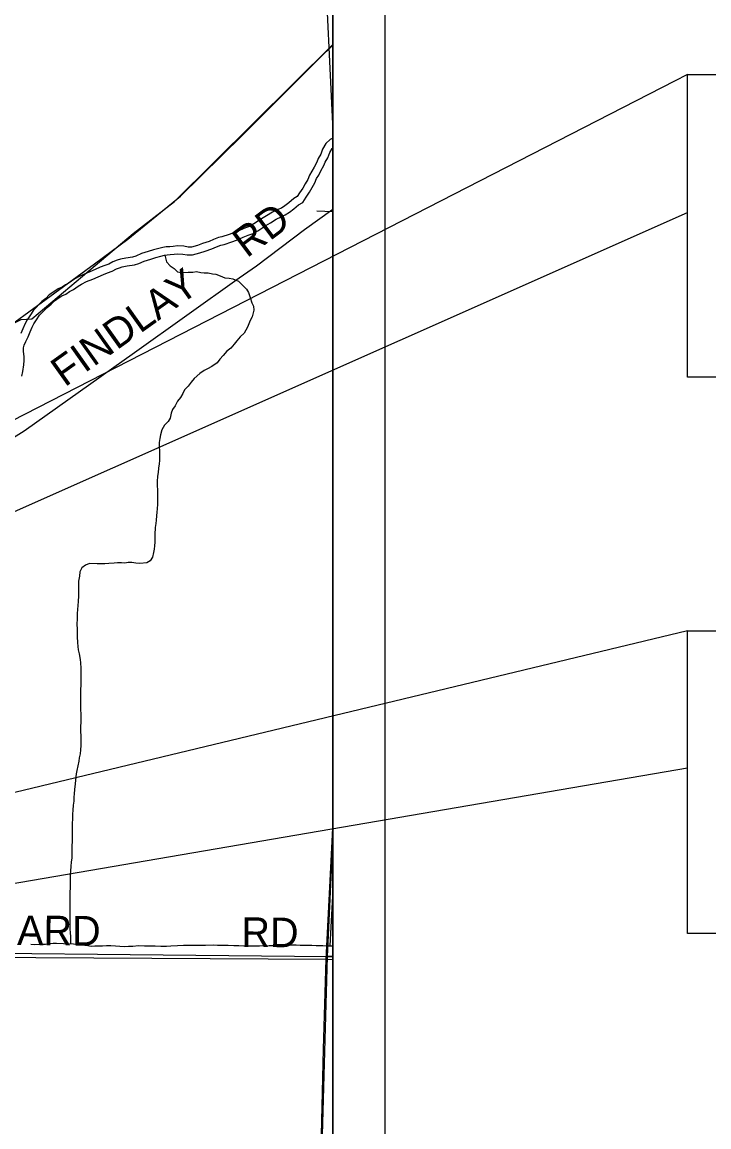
# Model space of a CAD drawing. Extents: x -8.3 to 42.1, y 0 to 22.
# Drawn here: x 8.304 to 9.622, y 16.982 to 19.103 of the extents above; entities that cross this region are included whole.
import ezdxf

# ---------------------------------------------------------------- set-up
doc = ezdxf.new("R2010")
doc.units = 0
for name, color, linetype in [('Default', 7, 'Continuous'), ('GM_X_County_Road', 7, 'Continuous'), ('GM_X_County_Road_Text', 7, 'Continuous'), ('GM_X_Major_River', 7, 'Continuous'), ('GM_X_Minor_River', 7, 'Continuous'), ('GM_X_Rail_Line', 7, 'Continuous'), ('GM_X_Section', 7, 'Continuous'), ('GM_X_State_Route', 7, 'Continuous'), ('GM_X_Township_Road', 7, 'Continuous'), ('SH_Cut_Line', 7, 'Continuous'), ('SH_Data', 7, 'Continuous'), ('SH_Text', 7, 'Continuous')]:
    doc.layers.add(name, color=color, linetype=linetype)

msp = doc.modelspace()

# ---------------------------------------------------------------- linework, layer by layer
at = {"layer": 'Default'}
for points in [[(8.9, 18.8937), (8.9, 19.2548), (8.8831, 19.2542)], [(8.9, 17.309), (8.9, 17.5442), (8.8895, 17.3091)], [(8.9, 16.3044), (8.9, 17.309), (8.8895, 17.3091), (8.8613, 16.3047)]]:
    msp.add_lwpolyline(points, close=True, dxfattribs=at)
at = {"layer": 'GM_X_County_Road'}
for points in [[(7.8987, 17.8473), (7.933, 17.8784), (7.9603, 17.9099), (7.9717, 17.9213), (7.9812, 17.9331), (7.9926, 17.9548), (8.0656, 18.0756), (8.2076, 18.2177), (8.2873, 18.3051), (8.3078, 18.3181), (8.5197, 18.4682), (8.7205, 18.6119), (8.7539, 18.6347), (8.8458, 18.7042), (8.9, 18.7436)], [(7.8831, 17.31), (8.8875, 17.3037), (8.9, 17.3036)]]:
    msp.add_lwpolyline(points, dxfattribs=at)
at = {"layer": 'GM_X_Major_River'}
for points in [[(8.9, 18.8798), (8.8953, 18.8772), (8.8867, 18.8695), (8.8806, 18.8585), (8.8769, 18.849), (8.872, 18.8406), (8.8693, 18.8338), (8.8641, 18.8242), (8.8599, 18.8162), (8.8554, 18.809), (8.852, 18.8006), (8.8471, 18.7923), (8.8426, 18.7839), (8.8362, 18.7747), (8.832, 18.7679), (8.8252, 18.7641), (8.8157, 18.7557), (8.8082, 18.7499)], [(8.8173, 18.7378), (8.8254, 18.7439), (8.8341, 18.7516), (8.8429, 18.7566), (8.8489, 18.7665), (8.8555, 18.7759), (8.8603, 18.7848), (8.8656, 18.7939), (8.8689, 18.8021), (8.8731, 18.8087), (8.8774, 18.8171), (8.8831, 18.8273), (8.8857, 18.834), (8.8905, 18.8423), (8.8944, 18.852), (8.8987, 18.8599), (8.9, 18.8611)], [(8.8082, 18.7499), (8.8017, 18.7457), (8.7945, 18.7426), (8.7843, 18.7376), (8.7726, 18.7304), (8.7635, 18.725), (8.7484, 18.7151), (8.7404, 18.7105), (8.7325, 18.7074), (8.7226, 18.7035), (8.7097, 18.6982), (8.701, 18.6951), (8.6874, 18.6901), (8.6809, 18.6889), (8.6711, 18.685), (8.6627, 18.6816), (8.6502, 18.6773), (8.6404, 18.6739), (8.629, 18.6708), (8.6222, 18.6707), (8.6142, 18.6722), (8.6017, 18.6733), (8.5937, 18.6721), (8.5873, 18.6713), (8.5801, 18.6713), (8.5736, 18.6697), (8.5664, 18.6682), (8.5558, 18.6655), (8.5459, 18.662), (8.5327, 18.6581), (8.5221, 18.6535), (8.5156, 18.6512), (8.5031, 18.6496), (8.4925, 18.6473), (8.486, 18.6457), (8.4781, 18.6427), (8.4701, 18.6381), (8.4622, 18.6354), (8.4538, 18.6319), (8.444, 18.6277), (8.4338, 18.6234), (8.4213, 18.6184), (8.4107, 18.6131), (8.4031, 18.6085), (8.394, 18.6024), (8.3868, 18.5981), (8.3804, 18.5939), (8.3728, 18.5905), (8.3664, 18.5863), (8.3558, 18.579), (8.3493, 18.5721), (8.3418, 18.566), (8.3255, 18.5496), (8.3184, 18.5389), (8.3135, 18.5309), (8.3093, 18.5241), (8.3052, 18.5138), (8.3014, 18.5047)], [(8.3029, 18.423), (8.3052, 18.4321), (8.3072, 18.4449), (8.3077, 18.453), (8.3076, 18.4608), (8.3065, 18.4706), (8.3064, 18.4771), (8.3079, 18.4823), (8.3107, 18.4893), (8.3152, 18.4984), (8.3192, 18.5081), (8.3229, 18.5173), (8.3264, 18.5231), (8.3311, 18.5308), (8.3373, 18.54), (8.352, 18.5548), (8.3597, 18.561), (8.3657, 18.5674), (8.3748, 18.5737), (8.3801, 18.5772), (8.3877, 18.5806), (8.3948, 18.5852), (8.4021, 18.5895), (8.4113, 18.5957), (8.418, 18.5998), (8.4275, 18.6046), (8.4395, 18.6094), (8.4499, 18.6137), (8.4597, 18.6179), (8.4675, 18.6212), (8.4764, 18.6242), (8.4847, 18.6289), (8.4906, 18.6312), (8.4959, 18.6325), (8.5057, 18.6347), (8.5192, 18.6364), (8.5277, 18.6394), (8.5378, 18.6438), (8.5506, 18.6476), (8.5602, 18.6509), (8.5699, 18.6534), (8.577, 18.6549), (8.5819, 18.6561), (8.5882, 18.6562), (8.5957, 18.6571), (8.6021, 18.658), (8.6122, 18.6572), (8.6208, 18.6556), (8.6311, 18.6556), (8.6449, 18.6594), (8.6552, 18.663), (8.6681, 18.6674), (8.6767, 18.671), (8.6851, 18.6742), (8.6914, 18.6754), (8.7061, 18.6808), (8.7152, 18.684), (8.7283, 18.6895), (8.7379, 18.6933), (8.747, 18.6968), (8.7563, 18.7022), (8.7715, 18.7121), (8.7804, 18.7174), (8.7917, 18.7244), (8.8009, 18.7288), (8.8089, 18.7323), (8.8173, 18.7378)]]:
    msp.add_lwpolyline(points, dxfattribs=at)
at = {"layer": 'GM_X_Minor_River'}
for p, q in [((8.8695, 18.74), (8.9, 18.7391)), ((8.9, 17.4372), (8.8945, 17.3293))]:
    msp.add_line(p, q, dxfattribs=at)
for points in [[(8.5778, 18.6551), (8.5809, 18.6421), (8.5882, 18.6349), (8.5954, 18.6296), (8.6022, 18.6232), (8.6095, 18.6221), (8.6227, 18.6225), (8.6315, 18.6226), (8.6383, 18.6238), (8.647, 18.6219), (8.6535, 18.6212), (8.6611, 18.6212), (8.669, 18.6194), (8.6759, 18.6186), (8.6842, 18.6157), (8.6926, 18.6119), (8.7013, 18.6108), (8.7085, 18.6097), (8.7188, 18.6052), (8.726, 18.5984), (8.7344, 18.5901), (8.7382, 18.5833), (8.7413, 18.5742), (8.7448, 18.5636), (8.7478, 18.5572), (8.7486, 18.5496), (8.7456, 18.537), (8.7415, 18.5298), (8.7366, 18.5172), (8.7298, 18.5058), (8.7226, 18.4982), (8.7162, 18.4909), (8.7105, 18.4841), (8.7041, 18.4768), (8.6965, 18.4707), (8.6897, 18.4627), (8.6833, 18.4555), (8.678, 18.4486), (8.6682, 18.4417), (8.6595, 18.4371), (8.6531, 18.4337), (8.6447, 18.4279), (8.6341, 18.4184), (8.6285, 18.4115), (8.6224, 18.4039), (8.6156, 18.3966), (8.6122, 18.3894), (8.6077, 18.3822), (8.6021, 18.3749), (8.5975, 18.3662), (8.5926, 18.3593), (8.5896, 18.3517), (8.5878, 18.3426), (8.584, 18.3357), (8.5768, 18.3289), (8.5719, 18.3197), (8.5693, 18.3106), (8.5682, 18.3034), (8.5667, 18.2954), (8.5671, 18.2871), (8.5675, 18.2799), (8.5672, 18.273), (8.5672, 18.2613), (8.5668, 18.2544), (8.5654, 18.2461), (8.565, 18.2381), (8.5639, 18.2312), (8.5632, 18.221), (8.5633, 18.1967), (8.5637, 18.1899), (8.5633, 18.1773), (8.563, 18.1686), (8.5626, 18.1621), (8.5619, 18.1546), (8.5612, 18.1466), (8.5601, 18.1401), (8.5593, 18.1325), (8.5583, 18.1192), (8.5583, 18.1044), (8.558, 18.0976), (8.5572, 18.0908), (8.5561, 18.0843), (8.5542, 18.0756), (8.5497, 18.0687), (8.5433, 18.0649), (8.53, 18.0637), (8.5217, 18.064), (8.5141, 18.0651), (8.5076, 18.0651), (8.5008, 18.0643), (8.4943, 18.0646), (8.4871, 18.0646), (8.4803, 18.0642), (8.4704, 18.0633), (8.4625, 18.0629), (8.448, 18.0628), (8.4329, 18.0635), (8.4253, 18.0604), (8.4185, 18.0551), (8.4147, 18.0475), (8.4136, 18.0391)], [(8.4136, 18.0391), (8.4121, 18.0293), (8.4122, 18.0004), (8.4115, 17.9909), (8.4104, 17.9822), (8.4101, 17.9757), (8.4093, 17.967), (8.4094, 17.9575), (8.409, 17.9469), (8.4094, 17.9374), (8.4091, 17.9298), (8.4095, 17.9229), (8.4099, 17.9119), (8.4107, 17.9044), (8.4115, 17.8979), (8.413, 17.8899), (8.415, 17.8793), (8.4158, 17.8725), (8.4162, 17.8626), (8.4166, 17.8562), (8.4166, 17.8482), (8.4163, 17.8402), (8.4163, 17.8323), (8.416, 17.819), (8.416, 17.8064), (8.4157, 17.7958), (8.4157, 17.7894), (8.4161, 17.7829), (8.4165, 17.7742), (8.4162, 17.7677), (8.4162, 17.759), (8.4155, 17.7506), (8.4159, 17.7427), (8.4163, 17.7305), (8.4167, 17.7229), (8.4167, 17.7142), (8.416, 17.7058), (8.4149, 17.6982), (8.4134, 17.6906), (8.4123, 17.6838), (8.4108, 17.6751), (8.409, 17.6663), (8.4078, 17.6599), (8.406, 17.6477), (8.4053, 17.6405), (8.4042, 17.6295), (8.4038, 17.6211), (8.4031, 17.6147), (8.4027, 17.6071), (8.402, 17.5995), (8.4009, 17.59), (8.4006, 17.5824), (8.4002, 17.5733), (8.3999, 17.5645), (8.3995, 17.5577), (8.3996, 17.5399), (8.3996, 17.5304), (8.3993, 17.5209), (8.3989, 17.5102), (8.399, 17.4985), (8.3982, 17.4901), (8.3975, 17.4825), (8.3964, 17.4727), (8.3961, 17.4662), (8.3961, 17.4457), (8.3955, 17.4275), (8.3955, 17.4096), (8.3952, 17.4017), (8.3953, 17.3618), (8.3957, 17.355), (8.3965, 17.347), (8.3969, 17.3398), (8.3966, 17.3333)], [(8.3966, 17.3333), (8.392, 17.3322), (8.3829, 17.3333), (8.37, 17.334), (8.3632, 17.3339), (8.3488, 17.3323), (8.3416, 17.3319), (8.3275, 17.3318), (8.3203, 17.3322)], [(8.9, 17.3288), (8.8903, 17.3291), (8.8811, 17.3294), (8.8743, 17.3294), (8.8679, 17.3297), (8.8599, 17.3301), (8.85, 17.33), (8.8375, 17.3303), (8.8295, 17.3307), (8.8219, 17.3306), (8.8098, 17.3302), (8.8034, 17.3302), (8.7954, 17.3297), (8.7859, 17.3297), (8.7779, 17.3293), (8.7593, 17.3292), (8.7472, 17.3287), (8.7407, 17.3291), (8.7294, 17.329), (8.7195, 17.3297), (8.71, 17.3297), (8.699, 17.3304), (8.6785, 17.3303), (8.6702, 17.3306), (8.6557, 17.3305), (8.6455, 17.3301), (8.6326, 17.3304), (8.6227, 17.3304), (8.6136, 17.3299), (8.6019, 17.3295), (8.5894, 17.3287), (8.5806, 17.3286), (8.57, 17.3282), (8.559, 17.3289), (8.5457, 17.3292), (8.5389, 17.3291), (8.5271, 17.3295), (8.5161, 17.3286), (8.5082, 17.3282), (8.4994, 17.3278), (8.4915, 17.3281), (8.4831, 17.3289), (8.474, 17.3296), (8.466, 17.3295), (8.4581, 17.3291), (8.4436, 17.329), (8.4361, 17.3286), (8.4296, 17.3297), (8.3966, 17.3333)]]:
    msp.add_lwpolyline(points, dxfattribs=at)
at = {"layer": 'GM_X_Rail_Line'}
msp.add_lwpolyline([(7.9103, 18.3409), (8.3022, 18.5316), (8.3223, 18.533), (8.5169, 18.6965), (8.5964, 18.7584), (8.9, 19.0594)], dxfattribs=at)
at = {"layer": 'GM_X_Section'}
msp.add_lwpolyline([(7.8808, 17.3192), (8.8895, 17.3091), (8.8613, 16.3047), (7.8576, 16.3068), (7.8577, 16.3121), (7.8807, 17.3166)], close=True, dxfattribs=at)
at = {"layer": 'GM_X_State_Route'}
msp.add_lwpolyline([(7.9083, 18.1745), (7.9462, 18.2196), (8.1416, 18.3992), (8.2566, 18.5029), (8.4426, 18.6386), (8.5067, 18.6856), (8.6077, 18.7682), (8.7266, 18.8854), (8.8749, 19.0334), (8.9, 19.058)], dxfattribs=at)
at = {"layer": 'GM_X_Township_Road'}
msp.add_line((8.8875, 17.3037), (8.9, 17.5556), dxfattribs=at)
for points in [[(8.9, 16.8007), (8.9, 20.9)], [(8.8745, 16.8004), (8.882, 17.1313), (8.8875, 17.3037)]]:
    msp.add_lwpolyline(points, dxfattribs=at)
at = {"layer": 'SH_Cut_Line'}
msp.add_lwpolyline([(8.9, 14.1), (8.9, 20.9)], dxfattribs=at)
at = {"layer": 'SH_Data'}
for p, q in [((9, 21), (9, 14)), ((8.9, 20.9), (8.9, 14.1))]:
    msp.add_line(p, q, dxfattribs=at)
at = {"layer": 'SH_Text'}
for points in [[(9.5811, 19.002), (5.7134, 17.0195), (9.5811, 18.737)], [(9.5811, 19.002), (11.1405, 19.002), (11.1405, 18.4209), (9.5811, 18.4209)], [(9.5811, 17.9343), (5.7594, 17.0162), (9.5811, 17.6715)], [(9.5811, 17.9343), (11.1405, 17.9343), (11.1405, 17.3531), (9.5811, 17.3531)]]:
    msp.add_lwpolyline(points, close=True, dxfattribs=at)

# ---------------------------------------------------------------- texts
at = {"layer": 'GM_X_County_Road_Text'}
for s, rotation, p in [('RD', 36.7812, (8.735, 18.6486)), ('FINDLAY', 35.4665, (8.3856, 18.401)), ('HUBBARD', 359.5779, (8.0828, 17.3326)), ('RD', 359.5045, (8.7245, 17.3276))]:
    msp.add_text(s, height=0.05682, rotation=rotation, dxfattribs=at).set_placement(p)

doc.saveas('drawing.dxf')
